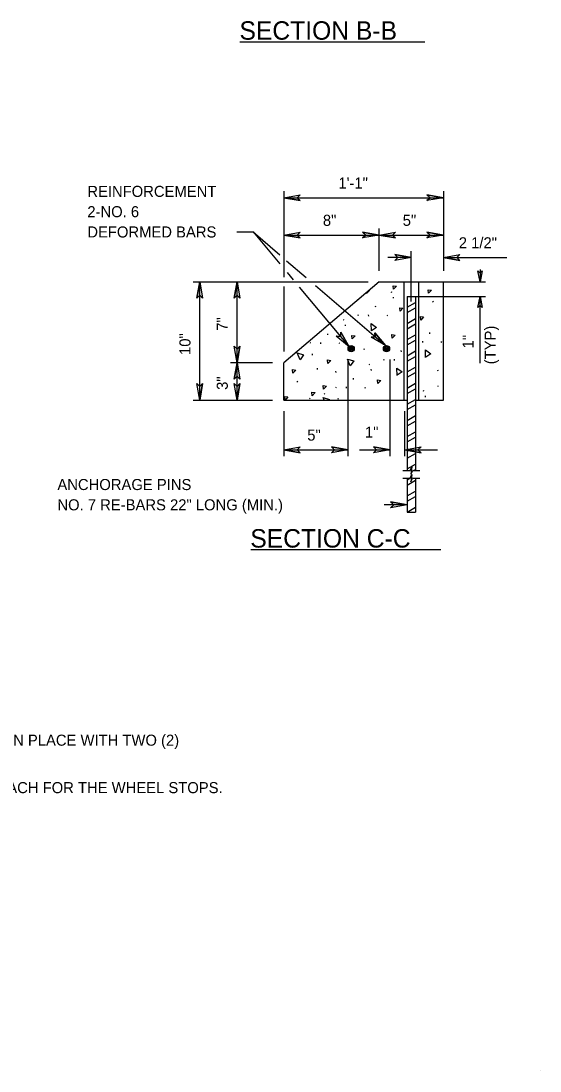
# Model space of a CAD drawing. Extents: x 12.4 to 19.6, y 6 to 16.2.
# Drawn here: x 16.81 to 19.62, y 5.98 to 11.68 of the extents above; entities that cross this region are included whole.
import ezdxf

# ---------------------------------------------------------------- set-up
doc = ezdxf.new("R2010")
doc.units = 0
for name, color, linetype in [('Default', 7, 'Continuous'), ('DETL-DIMS', 7, 'Continuous'), ('DETL-LINE', 7, 'Continuous'), ('DETL-NOTE', 7, 'Continuous'), ('DETL-PATT', 7, 'Continuous'), ('DETL-TITL', 7, 'Continuous'), ('TTLB-TEXT', 7, 'Continuous')]:
    doc.layers.add(name, color=color, linetype=linetype)

# ---------------------------------------------------------------- blocks, each defined once
blk = doc.blocks.new('LTERMF')
at = {"layer": 'Default'}
blk.add_lwpolyline([(-0.12, 0.021), (0, 0), (-0.12, -0.021), (-0.097, 0)], close=True, dxfattribs=at)

msp = doc.modelspace()

# ---------------------------------------------------------------- linework, layer by layer
at = {"layer": 'DETL-DIMS'}
for p, q in [((18.2308, 10.7545), (18.2308, 10.2889)), ((18.2308, 10.7195), (18.3202, 10.7353)), ((18.2308, 10.7195), (19.097, 10.7195)), ((18.2308, 10.7195), (18.3202, 10.7038)), ((18.3033, 10.7195), (18.3202, 10.7353)), ((18.3202, 10.7038), (18.3033, 10.7195)), ((19.097, 10.7195), (19.0077, 10.7353)), ((19.0077, 10.7353), (19.0245, 10.7195)), ((19.097, 10.7195), (19.0077, 10.7038)), ((19.0245, 10.7195), (19.0077, 10.7038)), ((19.097, 10.7545), (19.097, 10.3239)), ((17.9758, 10.5339), (18.065, 10.5339)), ((18.065, 10.5339), (18.209, 10.3614)), ((18.065, 10.5339), (18.2102, 10.4091)), ((18.2308, 10.517), (18.3202, 10.5328)), ((18.3033, 10.517), (18.3202, 10.5328)), ((18.7483, 10.517), (18.6589, 10.5328)), ((18.6589, 10.5328), (18.6758, 10.517)), ((18.7483, 10.3239), (18.7483, 10.552)), ((18.7483, 10.517), (18.8377, 10.5328)), ((18.8208, 10.517), (18.8377, 10.5328)), ((19.097, 10.517), (19.0077, 10.5328)), ((19.0077, 10.5328), (19.0245, 10.517)), ((18.2308, 10.517), (18.7483, 10.517)), ((18.2308, 10.517), (18.3202, 10.5013)), ((18.3202, 10.5013), (18.3033, 10.517)), ((18.7483, 10.517), (18.6589, 10.5013)), ((18.6758, 10.517), (18.6589, 10.5013)), ((18.7483, 10.517), (19.097, 10.517)), ((18.7483, 10.517), (18.8377, 10.5013)), ((18.8377, 10.5013), (18.8208, 10.517)), ((19.097, 10.517), (19.0077, 10.5013)), ((19.0245, 10.517), (19.0077, 10.5013)), ((18.9227, 10.1564), (18.9227, 10.4301)), ((18.2464, 10.378), (18.353, 10.2865)), ((18.9227, 10.3951), (18.7953, 10.3951)), ((18.9227, 10.3951), (18.8333, 10.4109)), ((18.8333, 10.4109), (18.8502, 10.3951)), ((18.9227, 10.3951), (18.8333, 10.3794)), ((18.8502, 10.3951), (18.8333, 10.3794)), ((19.097, 10.3951), (19.1864, 10.4109)), ((19.097, 10.3951), (19.4409, 10.3951)), ((19.097, 10.3951), (19.1864, 10.3794)), ((19.1695, 10.3951), (19.1864, 10.4109)), ((19.1864, 10.3794), (19.1695, 10.3951)), ((18.2489, 10.3136), (18.2825, 10.2735)), ((19.2957, 10.3306), (19.2957, 10.2639)), ((17.7402, 10.2639), (18.6883, 10.2639)), ((17.7752, 10.2639), (17.7594, 10.1745)), ((17.7752, 9.6226), (17.7752, 10.2639)), ((17.7752, 10.2639), (17.7909, 10.1745)), ((17.9777, 10.2639), (17.9619, 10.1745)), ((17.9777, 9.8251), (17.9777, 10.2639)), ((17.9777, 10.2639), (17.9934, 10.1745)), ((18.9302, 10.2639), (19.3257, 10.2639)), ((17.7594, 10.1745), (17.7752, 10.1914)), ((17.7752, 10.1914), (17.7909, 10.1745)), ((17.9619, 10.1745), (17.9777, 10.1914)), ((17.9777, 10.1914), (17.9934, 10.1745)), ((18.2308, 10.2389), (18.2308, 9.8851)), ((18.3153, 10.2343), (18.5852, 9.9111)), ((18.4032, 10.2435), (18.7825, 9.9175)), ((18.9302, 10.1841), (19.3257, 10.1841)), ((19.2957, 9.8224), (19.2957, 10.1841)), ((18.5852, 9.9111), (18.5158, 9.9696)), ((18.5387, 9.9668), (18.5158, 9.9696)), ((18.5399, 9.9899), (18.5387, 9.9668)), ((18.5852, 9.9111), (18.5399, 9.9899)), ((18.7275, 9.9648), (18.7045, 9.9638)), ((18.7825, 9.9175), (18.7045, 9.9638)), ((18.7825, 9.9175), (18.725, 9.9878)), ((18.725, 9.9878), (18.7275, 9.9648)), ((17.9777, 9.8251), (17.9619, 9.9145)), ((17.9777, 9.8976), (17.9619, 9.9145)), ((17.9777, 9.8251), (17.9934, 9.9145)), ((17.9934, 9.9145), (17.9777, 9.8976)), ((18.1708, 9.8251), (17.9427, 9.8251)), ((17.9777, 9.8251), (17.9619, 9.7358)), ((17.9777, 9.6226), (17.9777, 9.8251)), ((17.9777, 9.8251), (17.9934, 9.7358)), ((18.5789, 9.8415), (18.5789, 9.3176)), ((18.8072, 9.8415), (18.8072, 9.3176)), ((17.9619, 9.7358), (17.9777, 9.7526)), ((17.9777, 9.7526), (17.9934, 9.7358)), ((17.7752, 9.6226), (17.7594, 9.712)), ((17.7752, 9.6951), (17.7594, 9.712)), ((17.7752, 9.6226), (17.7909, 9.712)), ((17.7909, 9.712), (17.7752, 9.6951)), ((17.9777, 9.6226), (17.9619, 9.712)), ((17.9777, 9.6951), (17.9619, 9.712)), ((17.9777, 9.6226), (17.9934, 9.712)), ((17.9934, 9.712), (17.9777, 9.6951)), ((17.7402, 9.6226), (18.1708, 9.6226)), ((18.2308, 9.5626), (18.2308, 9.3176)), ((18.8862, 9.5626), (18.8862, 9.3176)), ((18.2308, 9.3526), (18.3202, 9.3684)), ((18.2308, 9.3526), (18.5789, 9.3526)), ((18.2308, 9.3526), (18.3202, 9.3369)), ((18.3033, 9.3526), (18.3202, 9.3684)), ((18.3202, 9.3369), (18.3033, 9.3526)), ((18.5789, 9.3526), (18.4895, 9.3684)), ((18.4895, 9.3684), (18.5064, 9.3526)), ((18.5789, 9.3526), (18.4895, 9.3369)), ((18.5064, 9.3526), (18.4895, 9.3369)), ((18.6418, 9.3526), (18.8072, 9.3526)), ((18.8072, 9.3526), (18.7178, 9.3684)), ((18.7178, 9.3684), (18.7347, 9.3526)), ((18.8072, 9.3526), (18.7178, 9.3369)), ((18.7347, 9.3526), (18.7178, 9.3369)), ((18.8862, 9.3526), (18.9755, 9.3684)), ((18.8862, 9.3526), (19.064, 9.3526)), ((18.8862, 9.3526), (18.9755, 9.3369)), ((18.9587, 9.3526), (18.9755, 9.3684)), ((18.9755, 9.3369), (18.9587, 9.3526)), ((18.9002, 9.0544), (18.7753, 9.0544)), ((18.9002, 9.0544), (18.8108, 9.0701)), ((18.8108, 9.0701), (18.8277, 9.0544)), ((18.9002, 9.0544), (18.8108, 9.0386)), ((18.8277, 9.0544), (18.8108, 9.0386))]:
    msp.add_line(p, q, dxfattribs=at)
for points in [[(18.3202, 10.7038), (18.2308, 10.7195), (18.3202, 10.7353), (18.3033, 10.7195)], [(19.0077, 10.7353), (19.097, 10.7195), (19.0077, 10.7038), (19.0245, 10.7195)], [(18.3202, 10.5013), (18.2308, 10.517), (18.3202, 10.5328), (18.3033, 10.517)], [(18.6589, 10.5328), (18.7483, 10.517), (18.6589, 10.5013), (18.6758, 10.517)], [(18.8377, 10.5013), (18.7483, 10.517), (18.8377, 10.5328), (18.8208, 10.517)], [(19.0077, 10.5328), (19.097, 10.517), (19.0077, 10.5013), (19.0245, 10.517)], [(18.8333, 10.4109), (18.9227, 10.3951), (18.8333, 10.3794), (18.8502, 10.3951)], [(19.1864, 10.3794), (19.097, 10.3951), (19.1864, 10.4109), (19.1695, 10.3951)], [(17.7594, 10.1745), (17.7752, 10.2639), (17.7909, 10.1745), (17.7752, 10.1914)], [(17.9619, 10.1745), (17.9777, 10.2639), (17.9934, 10.1745), (17.9777, 10.1914)], [(18.5399, 9.9899), (18.5852, 9.9111), (18.5158, 9.9696), (18.5387, 9.9668)], [(18.725, 9.9878), (18.7825, 9.9175), (18.7045, 9.9638), (18.7275, 9.9648)], [(17.9934, 9.9145), (17.9777, 9.8251), (17.9619, 9.9145), (17.9777, 9.8976)], [(17.9619, 9.7358), (17.9777, 9.8251), (17.9934, 9.7358), (17.9777, 9.7526)], [(17.7909, 9.712), (17.7752, 9.6226), (17.7594, 9.712), (17.7752, 9.6951)], [(17.9934, 9.712), (17.9777, 9.6226), (17.9619, 9.712), (17.9777, 9.6951)], [(18.3202, 9.3369), (18.2308, 9.3526), (18.3202, 9.3684), (18.3033, 9.3526)], [(18.4895, 9.3684), (18.5789, 9.3526), (18.4895, 9.3369), (18.5064, 9.3526)], [(18.7178, 9.3684), (18.8072, 9.3526), (18.7178, 9.3369), (18.7347, 9.3526)], [(18.9755, 9.3369), (18.8862, 9.3526), (18.9755, 9.3684), (18.9587, 9.3526)], [(18.8108, 9.0701), (18.9002, 9.0544), (18.8108, 9.0386), (18.8277, 9.0544)]]:
    msp.add_lwpolyline(points, close=True, dxfattribs=at)
at = {"layer": 'DETL-LINE'}
for p, q in [((18.7483, 10.2639), (18.2308, 9.8251)), ((18.7483, 10.2639), (18.9002, 10.2639)), ((18.8815, 10.2639), (18.8815, 9.6226)), ((18.9002, 10.2639), (18.9452, 10.2639)), ((18.9452, 10.2639), (19.097, 10.2639)), ((18.9624, 10.2639), (18.9624, 9.6226)), ((19.097, 9.6226), (19.097, 10.2639)), ((18.9002, 10.1841), (18.9002, 9.3679)), ((18.9002, 10.1841), (18.9452, 10.1841)), ((18.9452, 10.1841), (18.9452, 9.3698)), ((18.2308, 9.6226), (18.2308, 9.8251)), ((18.2308, 9.6226), (18.9002, 9.6226)), ((18.9452, 9.6226), (19.097, 9.6226)), ((18.9002, 9.3679), (18.9002, 9.2401)), ((18.9452, 9.3698), (18.9452, 9.2401)), ((18.8768, 9.2401), (18.9163, 9.2401)), ((18.9302, 9.2401), (18.9684, 9.2401)), ((18.8773, 9.1986), (18.9158, 9.1986)), ((18.9002, 9.1986), (18.9002, 9.0151)), ((18.9297, 9.1986), (18.969, 9.1986)), ((18.9452, 9.1986), (18.9452, 9.0151)), ((18.9002, 9.0151), (18.9452, 9.0151))]:
    msp.add_line(p, q, dxfattribs=at)
for points in [[(18.9163, 9.2401), (18.9263, 9.2605), (18.9209, 9.2204), (18.9302, 9.2401)], [(18.9158, 9.1986), (18.9258, 9.219), (18.9204, 9.1789), (18.9297, 9.1986)]]:
    msp.add_lwpolyline(points, dxfattribs=at)
for centre, radius in [((18.5967, 9.9009), 0.0169), ((18.5967, 9.9009), 0.0127), ((18.5967, 9.9009), 0.00844), ((18.7882, 9.9016), 0.0169), ((18.7882, 9.9016), 0.0127), ((18.7882, 9.9016), 0.00844), ((18.5967, 9.9009), 0.00422), ((18.7882, 9.9016), 0.00422)]:
    msp.add_circle(centre, radius, dxfattribs=at)
at = {"layer": 'DETL-PATT'}
for p, q in [((18.8124, 10.2092), (18.8169, 10.2069)), ((18.6348, 10.1635), (18.6344, 10.1673)), ((18.8266, 10.1741), (18.8258, 10.1809)), ((18.9002, 10.1258), (18.9452, 10.1518)), ((19.0378, 10.1582), (19.0415, 10.1531)), ((18.6315, 10.0843), (18.636, 10.0821)), ((18.6922, 10.078), (18.6914, 10.0848)), ((18.7297, 10.1254), (18.729, 10.1322)), ((18.7895, 10.083), (18.7939, 10.0807)), ((18.9002, 10.0965), (18.9452, 10.1226)), ((18.5526, 10.0592), (18.5571, 10.0569)), ((18.5668, 10.0241), (18.566, 10.0309)), ((18.9002, 10.0381), (18.9452, 10.0641)), ((18.9002, 10.0089), (18.9452, 10.0349)), ((18.4699, 9.9754), (18.4692, 9.9822)), ((18.9002, 9.9505), (18.9452, 9.9764)), ((19.0235, 9.9816), (19.0228, 9.9884)), ((18.3717, 9.9343), (18.3762, 9.9321)), ((18.4323, 9.928), (18.4316, 9.9348)), ((18.5296, 9.933), (18.5341, 9.9307)), ((18.7743, 9.922), (18.7735, 9.9288)), ((18.9002, 9.9213), (18.9452, 9.9471)), ((18.9859, 9.9343), (18.9852, 9.9411)), ((19.0832, 9.9392), (19.0877, 9.937)), ((18.3878, 9.8662), (18.3871, 9.873)), ((18.6687, 9.8939), (18.668, 9.9007)), ((18.8692, 9.8838), (18.8684, 9.8906)), ((18.9002, 9.8628), (18.9452, 9.8886)), ((18.9002, 9.8335), (18.9452, 9.8594)), ((18.4139, 9.7886), (18.4132, 9.7954)), ((18.692, 9.8176), (18.6965, 9.8154)), ((18.771, 9.8428), (18.7754, 9.8406)), ((18.8316, 9.8365), (18.8309, 9.8433)), ((18.9002, 9.775), (18.9452, 9.801)), ((18.5144, 9.772), (18.5137, 9.7788)), ((18.6094, 9.7338), (18.6086, 9.7406)), ((18.7062, 9.7825), (18.7055, 9.7893)), ((18.9002, 9.7458), (18.9452, 9.7718)), ((18.9625, 9.7502), (18.9624, 9.7508)), ((19.068, 9.7782), (19.0673, 9.785)), ((18.3021, 9.7247), (18.3058, 9.7196)), ((18.5111, 9.6928), (18.5156, 9.6906)), ((18.5718, 9.6865), (18.5711, 9.6933)), ((18.6691, 9.6914), (18.6736, 9.6892)), ((18.9002, 9.6874), (18.9452, 9.7134)), ((18.9002, 9.6581), (18.9452, 9.6841)), ((19.0647, 9.6991), (19.0692, 9.6969)), ((18.3704, 9.632), (18.3749, 9.6297)), ((18.4494, 9.6571), (18.4538, 9.6549)), ((18.5273, 9.6247), (18.5265, 9.6315)), ((18.8082, 9.6523), (18.8074, 9.6591)), ((18.9002, 9.5996), (18.9452, 9.6256)), ((18.9858, 9.6739), (18.9903, 9.6717)), ((19, 9.6388), (18.9993, 9.6456)), ((18.9002, 9.5705), (18.9452, 9.5964)), ((18.9002, 9.512), (18.9452, 9.538)), ((18.9002, 9.4828), (18.9452, 9.5088)), ((18.9002, 9.4243), (18.9452, 9.4503)), ((18.9002, 9.3951), (18.9452, 9.421)), ((18.9002, 9.3074), (18.9452, 9.3334)), ((18.9002, 9.2489), (18.9452, 9.2749)), ((18.9355, 9.2401), (18.9452, 9.2456)), ((18.9002, 9.1905), (18.9142, 9.1986)), ((18.9002, 9.1613), (18.9452, 9.1873)), ((18.9002, 9.1028), (18.9452, 9.1288)), ((18.9002, 9.0735), (18.9452, 9.0995)), ((18.9002, 9.0151), (18.9452, 9.0411))]:
    msp.add_line(p, q, dxfattribs=at)
for points in [[(18.6801, 10.1994), (18.6796, 10.2056)], [(18.6929, 10.2169), (18.6958, 10.2165), (18.6801, 10.1994)], [(18.8267, 10.223), (18.8252, 10.2422), (18.8425, 10.2401), (18.8267, 10.223)], [(19.0159, 10.2016), (19.0144, 10.2207), (19.0316, 10.2187), (19.0159, 10.2016)], [(18.8616, 10.1038), (18.8601, 10.1229), (18.8773, 10.1209), (18.8616, 10.1038)], [(18.7067, 9.9976), (18.7053, 10.0376), (18.7342, 10.0167), (18.7073, 9.998)], [(18.9738, 10.0557), (18.9724, 10.0749), (18.9896, 10.0728), (18.9738, 10.0557)], [(18.6018, 9.9538), (18.6003, 9.9729), (18.6175, 9.9709), (18.6018, 9.9538)], [(18.8195, 9.9579), (18.818, 9.9771), (18.8353, 9.975), (18.8195, 9.9579)], [(18.3196, 9.8406), (18.3046, 9.8777), (18.3389, 9.8679), (18.3201, 9.8411)], [(19.0005, 9.8539), (18.999, 9.8939), (19.028, 9.873), (19.0011, 9.8543)], [(18.4705, 9.8207), (18.469, 9.8399), (18.4862, 9.8378), (18.4705, 9.8207)], [(18.5911, 9.808), (18.5761, 9.845), (18.6104, 9.8352), (18.5916, 9.8085)], [(18.8462, 9.7561), (18.8447, 9.7961), (18.8736, 9.7752), (18.8468, 9.7565)], [(18.2802, 9.7681), (18.2787, 9.7873), (18.2959, 9.7852), (18.2802, 9.7681)], [(18.4465, 9.6815), (18.4451, 9.7007), (18.4623, 9.6986), (18.4465, 9.6815)], [(18.7412, 9.7122), (18.7397, 9.7314), (18.7569, 9.7293), (18.7412, 9.7122)], [(18.2381, 9.6226), (18.2366, 9.6414), (18.2539, 9.6393), (18.2385, 9.6226)], [(18.3847, 9.6458), (18.3833, 9.665), (18.4005, 9.6629), (18.3847, 9.6458)], [(18.4495, 9.6226), (18.444, 9.6361), (18.4784, 9.6263), (18.4757, 9.6226)]]:
    msp.add_lwpolyline(points, dxfattribs=at)
at = {"layer": 'DETL-TITL'}
for p, q in [((17.9932, 11.5652), (18.9957, 11.5652)), ((18.0519, 8.8114), (19.0823, 8.8114))]:
    msp.add_line(p, q, dxfattribs=at)
at = {"layer": 'TTLB-TEXT'}
msp.add_line((19.6208, 5.9844), (19.6208, 5.9844), dxfattribs=at)

# ---------------------------------------------------------------- block references
at = {"layer": 'DETL-DIMS', "xscale": 0.5, "yscale": 0.5660377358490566}
for p, rotation in [((19.2957, 10.2639), -90), ((19.2957, 10.1841), 90)]:
    msp.add_blockref('LTERMF', p, dxfattribs=dict(at, rotation=rotation))

# ---------------------------------------------------------------- texts
at = {"layer": 'DETL-DIMS'}
for s, p in [('(TYP)', (19.3806, 9.8164)), ('1"', (19.2606, 9.9027))]:
    msp.add_text(s, height=0.06, rotation=90, dxfattribs=at).set_placement(p)
at = {"layer": 'DETL-NOTE'}
for s, p in [('1\'-1"', (18.5276, 10.7695)), ('REINFORCEMENT', (17.1657, 10.7239)), ('2-NO. 6', (17.1657, 10.6139)), ('8"', (18.4433, 10.567)), ('5"', (18.8763, 10.567)), ('DEFORMED BARS', (17.1657, 10.5039)), ('2 1/2"', (19.1803, 10.4451)), ('5"', (18.3585, 9.4026)), ('1"', (18.6715, 9.4184)), ('ANCHORAGE PINS', (17.0034, 9.1344)), ('NO. 7 RE-BARS 22" LONG (MIN.)', (17.0034, 9.0244)), ('1. PRECAST CONCRETE WHEEL STOPS SHALL BE LOCATED AS SHOWN ON THE PLANS, THEN SECURED IN PLACE WITH TWO (2)', (12.6215, 7.7482)), ('2. COST OF THE REINFORCEMENT BARS WILL BE INCIDENTAL TO THE CONTRACT UNIT PRICE BID PER EACH FOR THE WHEEL STOPS.', (12.6215, 7.4909))]:
    msp.add_text(s, height=0.06, dxfattribs=at).set_placement(p)
for s, p in [('7"', (17.9277, 9.9982)), ('10"', (17.7252, 9.8669)), ('3"', (17.9277, 9.6775))]:
    msp.add_text(s, height=0.06, rotation=90, dxfattribs=at).set_placement(p)
at = {"layer": 'DETL-TITL'}
for s, p in [('SECTION B-B', (17.9909, 11.5763)), ('SECTION C-C', (18.0496, 8.8225))]:
    msp.add_text(s, height=0.1, dxfattribs=at).set_placement(p)

doc.saveas('drawing.dxf')
